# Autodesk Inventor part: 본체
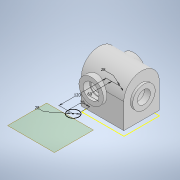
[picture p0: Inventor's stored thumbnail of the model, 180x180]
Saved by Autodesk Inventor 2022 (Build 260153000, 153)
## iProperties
Created: 2024-09
Part Number: 본체
Material: 일반
Document SubType Name: Modeling
Designer: PC-12
Density: 1 g/cm^3
Appearance: 기본값
Author: PC-12
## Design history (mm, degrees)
sketch "스케치1"
  geometry: L1 (-54.5, 45)-(54.5, 45); L2 (54.5, 45)-(54.5, -45); L3 (54.5, -45)-(-54.5, -45); L4 (-54.5, -45)-(-54.5, 45); L5 (-54.5, 45)-(54.5, -45); L6 (54.5, 45)-(-54.5, -45); 1 further point
  constraints: 12 end point, 2 midpoint, 2 parallel, 1 horizontal, 1 perpendicular
  dimensions: "d0" = 90 distance of L1.end L2.end; "d1" = 109 distance of L1.start L1.end
extrude "돌출1" new body sketch "스케치1" distance "d2" = 108; taper "d3" = 0 deg
sketch "스케치2"
  geometry: L1 (0, -54.5)-(0, 54.5) reference; L2 (0, 54.5)-(108, 54.5) reference; L3 (108, -54.5)-(108, 54.5) reference; L4 (0, -54.5)-(108, -54.5) reference; L5 (0, 0)-(-30.111, 0); L6 (9, 0)-(9, 36); L7 (9, 36)-(99, 36); L8 (99, 36)-(99, 16.5); L9 (99, 16.5)-(108, 16.5); L10 (108, 16.5)-(114, 16.5); L11 (114, 16.5)-(114, 0); L12 (114, 0)-(9, 0); L13 (114, 16.5)-(114, 28.5); L14 (114, 28.5)-(108, 28.5); L15 (108, 28.5)-(108, 16.5); 1 further point
  constraints: 22 end point, 5 perpendicular, 2 horizontal, 2 point on line, 2 vertical, 1 collinear, 1 horizontal alignment, 1 midpoint, 1 parallel
  dimensions: "d4" = 9 distance between parallel lines of L1 L6; "d6" = 9 distance between parallel lines of L3 L8; "d8" = 72 diameter of L7 L5; "d9" = 33 diameter of L9 L5; "d10" = 57 diameter of L14 L5; "d11" = 6 distance of L13.end L14.end; "d12" = 105 distance of L11.end L6.start (derived)
  node "투영된 루프1"
revolve "회전1" stored, may be unused: angle "d13" = 90 deg
revolve "회전2" stored, may be unused: angle "d14" = 90 deg
node "작업 평면1"
sketch "스케치3"
  geometry: L1 (-54.5, -45)-(54.5, -45) reference; L2 (-54.5, 45)-(-54.5, -45) reference; L3 (54.5, 45)-(-54.5, 45) reference; L4 (0, 105.252)-(0, -105.252); L5 (31, 54)-(31, 45); L6 (0, -107.467)-(0, -105.252); L7 (31, 54)-(20, 54); L8 (20, -54)-(31, -54); L9 (31, -54)-(31, -45); L10 (54.5, -45)-(54.5, 45) reference; L11 (20, 54)-(20, 38); L12 (20, -38)-(20, -54); L13 (20, 38)-(17.5, 38); L14 (17.5, 38)-(17.5, 31.46); L15 (20, -38)-(17.5, -38); L16 (17.5, -38)-(17.5, -31.46); L17 (20, 54)-(0, 54); L18 (20, -54)-(0, -54); L19 (31, -45)-(20, -45); L20 (-54.5, -45)-(54.5, -45) reference; L21 (31, 45)-(20, 45); L22 (54.5, 45)-(-54.5, 45) reference; A1 r 36 centre (0, 0) between (17.5, 31.46) and (17.5, -31.46) reference; 8 further points
  constraints: 32 end point, 8 point on line, 7 perpendicular, 2 horizontal, 1 coincident, 1 midpoint, 1 point on circle, 1 vertical, 2 other
  dimensions: "d17" = 62 diameter of L5 L4; "d19" = 62 diameter of L9 L4; "d23" = 108 distance of L8.end L5.start; "d24" = 54 vertical distance of point (0, 0) L5.start; "d25" = 16 distance of L11.end L7.end; "d26" = 16 distance of L12.start L8.start; "d27" = 35 diameter of L14 L4; "d28" = 35 diameter of L16 L4; "d29" = 40 diameter of L12 L4; "d30" = 40 diameter of L11 L4
  node "투영된 루프2"
  node "투영된 루프3"
revolve "회전3" stored, may be unused: angle "d31" = 90 deg
revolve "회전4" stored, may be unused: angle "d32" = 90 deg
fillet "모깎기2" dims "d33" = 45
node "작업 평면2"
sketch "스케치4"
  geometry: L1 (0, 90)-(0, 0) reference; L2 (0, 0)-(108, 0) reference; L3 (108, 90)-(108, 0) reference; L4 (0, 90)-(108, 90) reference; L5 (3, 90)-(65, 90) reference; C1 r 14 at (-6, 105); C2 r 14 at (-6, -15); 3 further points
  constraints: 2 centre point, 1 midpoint, 1 vertical alignment
  dimensions: "d40" = 28 diameter of C1; "d42" = 28 diameter of C2; "d43" = 120 distance of C1.centre C2.centre; "d44" = 60 vertical distance of point (0, 45) C2.centre; "d46" = 20 dimension on C1 L1
  node "투영된 루프4"
node "솔리드1"
other parameters: "d16" = 34, "d34" = 12
